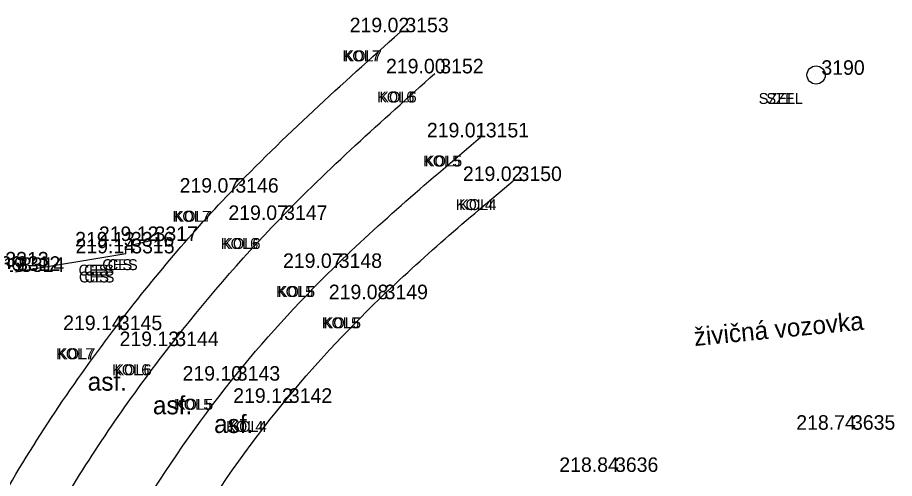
# Model space of a CAD drawing. Extents: x -471047 to -470889, y -1102859 to -1102000.
# Drawn here: x -470915.74 to -470891.64, y -1102012.74 to -1102000.06 of the extents above; entities that cross this region are included whole.
import ezdxf

# ---------------------------------------------------------------- set-up
doc = ezdxf.new("R2010")
doc.units = 0
for name, color, linetype in [('Vrstva 1', 7, 'Continuous'), ('Vrstva 22', 7, 'Continuous'), ('Vrstva 23', 7, 'Continuous'), ('Vrstva 34', 7, 'Continuous'), ('Vrstva 35', 7, 'Continuous'), ('Vrstva 36', 7, 'Continuous'), ('Vrstva 38', 7, 'Continuous'), ('Vrstva 8', 7, 'Continuous')]:
    doc.layers.add(name, color=color, linetype=linetype)

msp = doc.modelspace()

# ---------------------------------------------------------------- linework, layer by layer
at = {"layer": 'Vrstva 1'}
for points in [[(-470924.855, -1102053.304), (-470925.006, -1102047.44), (-470924.123, -1102041.506), (-470922.637, -1102034.36), (-470921.774, -1102030.337), (-470920.687, -1102025.449), (-470919.997, -1102022.703), (-470918.77, -1102018.928), (-470917.254, -1102015.371), (-470916.33, -1102013.583), (-470913.099, -1102008.664), (-470909.896, -1102004.881), (-470905.226, -1102000.466)], [(-470923.521, -1102053.19), (-470923.515, -1102047.615), (-470923.001, -1102043.415), (-470922.299, -1102039.934), (-470921.125, -1102034.455), (-470919.397, -1102026.547), (-470918.535, -1102023.012), (-470917.347, -1102019.378), (-470915.798, -1102015.782), (-470914.449, -1102013.323), (-470911.548, -1102009.097), (-470908.56, -1102005.632), (-470904.267, -1102001.603)], [(-470921.666, -1102053.966), (-470921.608, -1102047.528), (-470921.293, -1102044.721), (-470920.743, -1102041.873), (-470917.58, -1102027.088), (-470916.659, -1102023.359), (-470915.53, -1102020.079), (-470913.952, -1102016.506), (-470912.424, -1102013.741), (-470909.859, -1102010.048), (-470907.058, -1102006.954), (-470903.015, -1102003.355)], [(-470920.134, -1102054.704), (-470920.162, -1102048.671), (-470919.807, -1102044.881), (-470919.4, -1102042.641), (-470916.141, -1102027.446), (-470915.176, -1102023.614), (-470914.148, -1102020.628), (-470912.596, -1102017.149), (-470911.091, -1102014.432), (-470908.431, -1102010.663), (-470905.799, -1102007.808), (-470902.122, -1102004.556)]]:
    msp.add_spline(points, degree=3, dxfattribs=at)
at = {"layer": 'Vrstva 23'}
msp.add_circle((-470893.797, -1102001.644), 0.25, dxfattribs=at)
at = {"layer": 'Vrstva 34'}
for p, q in [((-470905.23, -1102000.47), (-470905.23, -1102000.47)), ((-470904.27, -1102001.6), (-470904.27, -1102001.6)), ((-470893.8, -1102001.64), (-470893.8, -1102001.64)), ((-470903.02, -1102003.36), (-470903.02, -1102003.36)), ((-470902.12, -1102004.56), (-470902.12, -1102004.56)), ((-470909.9, -1102004.88), (-470909.9, -1102004.88)), ((-470908.56, -1102005.63), (-470908.56, -1102005.63)), ((-470912.77, -1102006.36), (-470912.77, -1102006.36)), ((-470912.12, -1102006.21), (-470912.12, -1102006.21)), ((-470912.76, -1102006.55), (-470912.76, -1102006.55)), ((-470907.06, -1102006.95), (-470907.06, -1102006.95)), ((-470905.8, -1102007.81), (-470905.8, -1102007.81)), ((-470913.1, -1102008.66), (-470913.1, -1102008.66)), ((-470911.55, -1102009.1), (-470911.55, -1102009.1)), ((-470909.86, -1102010.05), (-470909.86, -1102010.05)), ((-470908.43, -1102010.66), (-470908.43, -1102010.66)), ((-470892.96, -1102011.4), (-470892.96, -1102011.4)), ((-470899.47, -1102012.56), (-470899.47, -1102012.56))]:
    msp.add_line(p, q, dxfattribs=at)
at = {"layer": 'Vrstva 8'}
for p, q in [((-470912.769, -1102006.357), (-470912.116, -1102006.209)), ((-470912.759, -1102006.555), (-470912.769, -1102006.357)), ((-470915.795, -1102007.059), (-470912.759, -1102006.555))]:
    msp.add_line(p, q, dxfattribs=at)

# ---------------------------------------------------------------- texts
at = {"layer": 'Vrstva 22'}
msp.add_text('živičná vozovka', height=0.5, rotation=5.5318, dxfattribs=at).set_placement((-470897.132, -1102009.098))
for p in [(-470913.807, -1102010.325), (-470912.017, -1102010.975), (-470910.336, -1102011.489)]:
    msp.add_text('asf.', height=0.5, dxfattribs=at).set_placement(p)
at = {"layer": 'Vrstva 35'}
for s, p in [('KOL7', (-470906.805, -1102001.27)), ('KOL7', (-470906.757, -1102001.27)), ('KOL6', (-470905.859, -1102002.4)), ('KOL6', (-470905.797, -1102002.4)), ('SZEL', (-470895.375, -1102002.44)), ('SZEL', (-470895.164, -1102002.44)), ('KOL5', (-470904.596, -1102004.16)), ('KOL5', (-470904.547, -1102004.16)), ('KOL4', (-470903.695, -1102005.36)), ('KOL4', (-470903.605, -1102005.36)), ('KOL7', (-470911.475, -1102005.68)), ('KOL7', (-470911.427, -1102005.68)), ('KOL6', (-470910.149, -1102006.43)), ('KOL6', (-470910.087, -1102006.43)), ('CES', (-470913.409, -1102007.01)), ('CES', (-470913.259, -1102007.01)), ('CES', (-470914.059, -1102007.16)), ('CES', (-470914.049, -1102007.35)), ('CES', (-470913.909, -1102007.16)), ('CES', (-470913.899, -1102007.35)), ('KOL5', (-470908.636, -1102007.75)), ('KOL5', (-470908.587, -1102007.75)), ('KOL5', (-470907.376, -1102008.61)), ('KOL5', (-470907.327, -1102008.61)), ('KOL7', (-470914.675, -1102009.46)), ('KOL7', (-470914.627, -1102009.46)), ('KOL6', (-470913.139, -1102009.9)), ('KOL6', (-470913.077, -1102009.9)), ('KOL5', (-470911.436, -1102010.85)), ('KOL5', (-470911.387, -1102010.85)), ('KOL4', (-470910.005, -1102011.46)), ('KOL4', (-470909.915, -1102011.46))]:
    msp.add_text(s, height=0.3, dxfattribs=at).set_placement(p)
at = {"layer": 'Vrstva 36'}
for s, p in [(' 3153', (-470905.23, -1102000.47)), (' 3152', (-470904.27, -1102001.6)), (' 3190', (-470893.8, -1102001.64)), (' 3151', (-470903.02, -1102003.36)), (' 3150', (-470902.12, -1102004.56)), (' 3146', (-470909.9, -1102004.88)), (' 3147', (-470908.56, -1102005.63)), (' 3317', (-470912.12, -1102006.21)), (' 3316', (-470912.77, -1102006.36)), (' 3315', (-470912.76, -1102006.55)), (' 3313', (-470916.22, -1102006.91)), (' 3148', (-470907.06, -1102006.95)), (' 3312', (-470915.9, -1102007.03)), (' 3314', (-470915.79, -1102007.06)), (' 3149', (-470905.8, -1102007.81)), (' 3145', (-470913.1, -1102008.66)), (' 3144', (-470911.55, -1102009.1)), (' 3143', (-470909.86, -1102010.05)), (' 3142', (-470908.43, -1102010.66)), (' 3635', (-470892.96, -1102011.4)), (' 3636', (-470899.47, -1102012.56))]:
    msp.add_text(s, height=0.4, dxfattribs=at).set_placement(p)
at = {"layer": 'Vrstva 38'}
for s, p in [('219.02 ', (-470906.611, -1102000.47)), ('219.00 ', (-470905.613, -1102001.6)), ('219.01 ', (-470904.49, -1102003.36)), ('219.02 ', (-470903.501, -1102004.56)), ('219.07 ', (-470911.283, -1102004.88)), ('219.07 ', (-470909.943, -1102005.63)), ('219.12 ', (-470913.501, -1102006.21)), ('219.13 ', (-470914.153, -1102006.36)), ('219.14 ', (-470914.142, -1102006.55)), ('219.07 ', (-470908.443, -1102006.95)), ('219.30 ', (-470917.243, -1102007.03)), ('219.19 ', (-470917.174, -1102007.06)), ('219.08 ', (-470907.184, -1102007.81)), ('219.14 ', (-470914.482, -1102008.66)), ('219.13 ', (-470912.933, -1102009.1)), ('219.10 ', (-470911.203, -1102010.05)), ('219.12 ', (-470909.811, -1102010.66)), ('218.74 ', (-470894.342, -1102011.4)), ('218.84 ', (-470900.852, -1102012.56))]:
    msp.add_text(s, height=0.4, dxfattribs=at).set_placement(p)

doc.saveas('drawing.dxf')
